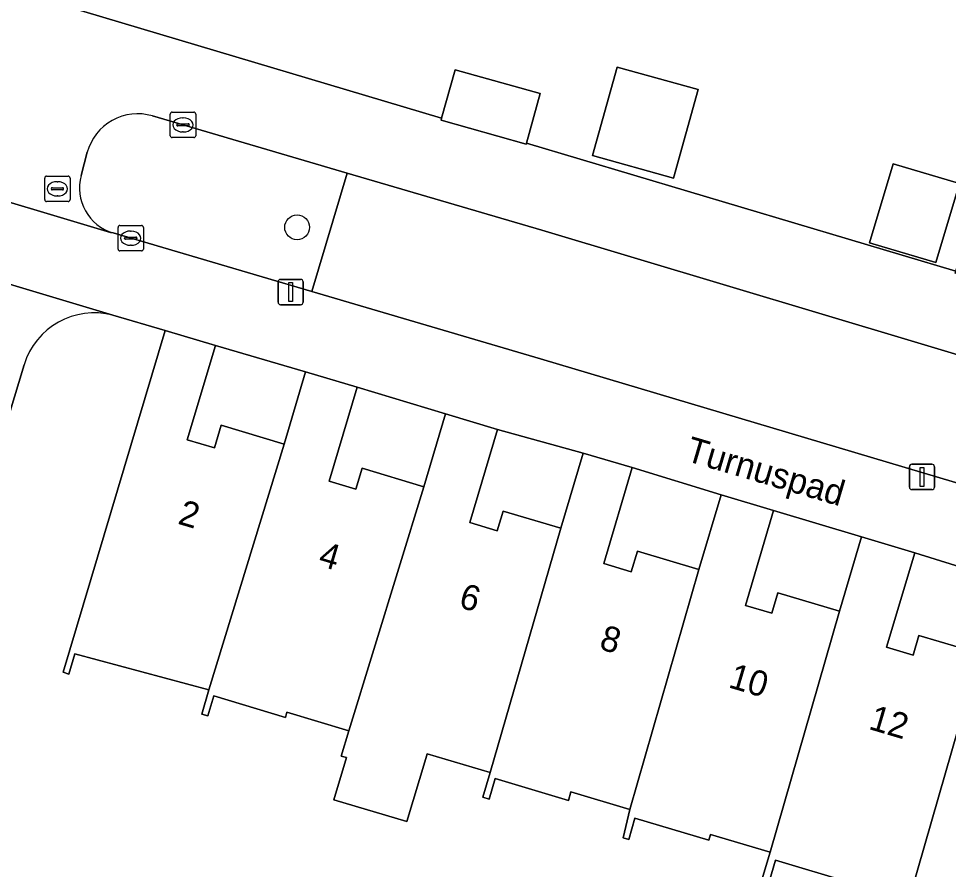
# Model space of a CAD drawing. Extents: x 162184 to 163154, y 385507 to 386516.
# Drawn here: x 162630.58 to 162667.22, y 386190.98 to 386224.51 of the extents above; entities that cross this region are included whole.
import ezdxf

# ---------------------------------------------------------------- set-up
doc = ezdxf.new("R2010")
doc.units = 0
for name, color, linetype in [('IMGEO_Boom', 7, 'Continuous'), ('IMGEO_Erf', 7, 'Continuous'), ('IMGEO_Groenvoorziening', 7, 'Continuous'), ('IMGEO_Kolk', 7, 'Continuous'), ('IMGEO_Lichtmast', 7, 'Continuous'), ('IMGEO_Openbare_ruimte_label', 7, 'Continuous'), ('IMGEO_Pand', 7, 'Continuous'), ('IMGEO_Pand_nummerreeks', 7, 'Continuous'), ('IMGEO_Rioolput', 7, 'Continuous'), ('IMGEO_Voetpad_open', 7, 'Continuous')]:
    doc.layers.add(name, color=color, linetype=linetype)

msp = doc.modelspace()

# ---------------------------------------------------------------- linework, layer by layer
at = {"layer": 'IMGEO_Boom'}
msp.add_circle((162641.558, 386216.282), 0.489, dxfattribs=at)
at = {"layer": 'IMGEO_Erf'}
for points in [[(162609.673, 386231.789), (162618.261, 386229.221), (162619.516, 386233.282), (162623.27, 386232.189), (162622.043, 386228.107), (162647.252, 386220.589), (162647.783, 386222.491), (162651.141, 386221.554), (162650.593, 386219.592), (162667.509, 386214.547), (162668.325, 386217.27), (162670.595, 386216.59), (162669.78, 386213.87), (162672.525, 386213.051), (162678.17, 386211.368)], [(162659.869, 386190.574), (162660.191, 386191.658), (162657.841, 386192.355), (162657.775, 386192.133), (162654.866, 386192.996), (162654.628, 386192.159), (162654.409, 386192.224), (162654.673, 386193.336), (162652.338, 386194.029), (162652.251, 386193.692), (162649.366, 386194.566), (162649.12, 386193.751), (162648.871, 386193.826), (162649.16, 386194.793), (162646.678, 386195.535), (162646.623, 386195.353), (162645.876, 386192.863), (162643.001, 386193.726), (162643.499, 386195.386), (162643.294, 386195.447), (162643.592, 386196.442), (162641.157, 386197.17), (162641.097, 386196.97), (162638.271, 386197.815), (162638.036, 386197.029), (162637.799, 386197.1), (162638.083, 386198.049), (162632.799, 386199.472), (162632.562, 386198.678), (162632.335, 386198.745), (162636.361, 386212.211), (162634.301, 386212.814)], [(162630.797, 386210.86), (162625.627, 386193.774)], [(162663.394, 386190.452), (162660.41, 386191.337), (162660.158, 386190.488)]]:
    msp.add_lwpolyline(points, dxfattribs=at)
for points in [[(162656.387, 386218.216), (162653.198, 386219.106), (162654.172, 386222.599), (162657.362, 386221.709)], [(162666.725, 386214.895), (162664.116, 386215.676), (162665.047, 386218.788), (162667.657, 386218.007)], [(162638.337, 386211.62), (162637.227, 386207.908), (162638.297, 386207.588), (162638.564, 386208.482), (162641.043, 386207.741), (162641.893, 386210.584)], [(162643.925, 386209.976), (162642.821, 386206.283), (162643.873, 386205.968), (162644.118, 386206.786), (162646.545, 386206.061), (162647.403, 386208.926)], [(162649.456, 386208.312), (162648.36, 386204.644), (162649.443, 386204.32), (162649.674, 386205.093), (162651.953, 386204.424), (162652.831, 386207.384)], [(162654.763, 386206.811), (162653.64, 386203.027), (162654.722, 386202.706), (162654.964, 386203.52), (162657.393, 386202.799), (162658.264, 386205.736)], [(162660.333, 386205.122), (162659.224, 386201.382), (162660.266, 386201.073), (162660.505, 386201.88), (162662.925, 386201.161), (162663.794, 386204.082)], [(162665.894, 386203.459), (162664.788, 386199.732), (162665.828, 386199.424), (162666.058, 386200.198), (162668.454, 386199.488), (162669.313, 386202.384)]]:
    msp.add_lwpolyline(points, close=True, dxfattribs=at)
msp.add_arc((162633.56, 386210.024), 2.887, 75.1335, 163.1588, dxfattribs=at)
at = {"layer": 'IMGEO_Groenvoorziening'}
for points in [[(162634.311, 386216.059), (162642.14, 386213.753), (162643.529, 386218.419), (162635.853, 386220.672)], [(162633.29, 386219.237), (162633.044, 386218.324)]]:
    msp.add_lwpolyline(points, dxfattribs=at)
msp.add_lwpolyline([(162669.521, 386210.679), (162651.203, 386216.166), (162643.529, 386218.419), (162642.14, 386213.753), (162651.146, 386211.101), (162668.123, 386206.04)], close=True, dxfattribs=at)
for centre, radius, start, end in [((162635.271, 386218.705), 2.051, 73.5107, 164.9774), ((162634.837, 386217.84), 1.857, 164.9037, 253.54)]:
    msp.add_arc(centre, radius, start, end, dxfattribs=at)
at = {"layer": 'IMGEO_Kolk'}
for p, q in [((162636.559, 386219.893), (162636.559, 386220.745)), ((162636.634, 386220.819), (162637.486, 386220.819)), ((162637.047, 386220.599), (162637.072, 386220.599)), ((162637.56, 386220.745), (162637.56, 386219.893)), ((162636.818, 386220.313), (162636.818, 386220.325)), ((162637.256, 386220.276), (162636.858, 386220.276)), ((162636.861, 386220.362), (162637.259, 386220.362)), ((162637.302, 386220.325), (162637.302, 386220.313)), ((162637.486, 386219.819), (162636.634, 386219.819)), ((162637.07, 386220.039), (162637.045, 386220.039)), ((162634.502, 386215.427), (162634.502, 386216.279)), ((162634.577, 386216.353), (162635.429, 386216.353)), ((162634.99, 386216.133), (162635.015, 386216.133)), ((162635.503, 386216.279), (162635.503, 386215.427)), ((162634.761, 386215.847), (162634.761, 386215.859)), ((162635.199, 386215.81), (162634.801, 386215.81)), ((162634.804, 386215.896), (162635.202, 386215.896)), ((162635.245, 386215.859), (162635.245, 386215.847)), ((162635.013, 386215.573), (162634.988, 386215.573)), ((162635.429, 386215.353), (162634.577, 386215.353))]:
    msp.add_line(p, q, dxfattribs=at)
for points in [[(162636.559, 386219.893), (162636.559, 386220.745)], [(162636.634, 386220.819), (162637.486, 386220.819)], [(162637.56, 386220.745), (162637.56, 386219.893)], [(162637.486, 386219.819), (162636.634, 386219.819)], [(162634.502, 386215.427), (162634.502, 386216.279)], [(162634.577, 386216.353), (162635.429, 386216.353)], [(162635.503, 386216.279), (162635.503, 386215.427)], [(162635.429, 386215.353), (162634.577, 386215.353)]]:
    msp.add_lwpolyline(points, dxfattribs=at)
for centre, radius, start, end in [((162636.636, 386220.743), 0.0765, 91.552, 178.448), ((162636.636, 386220.743), 0.0765, 91.552, 178.448), ((162637.484, 386220.743), 0.0765, 1.552, 88.448), ((162637.484, 386220.743), 0.0765, 1.552, 88.448), ((162636.858, 386220.322), 0.0403, 85.8775, 175.7526), ((162636.855, 386220.312), 0.0366, 178.938, 274.7102), ((162637.259, 386220.319), 0.043, 264.8664, 352.4533), ((162637.263, 386220.324), 0.0386, 1.7309, 96.639), ((162636.636, 386219.895), 0.0765, 181.552, 268.448), ((162636.636, 386219.895), 0.0765, 181.552, 268.448), ((162637.484, 386219.895), 0.0765, 271.552, 358.448), ((162637.484, 386219.895), 0.0765, 271.552, 358.448), ((162634.579, 386216.277), 0.0765, 91.552, 178.448), ((162634.579, 386216.277), 0.0765, 91.552, 178.448), ((162635.427, 386216.277), 0.0765, 1.552, 88.448), ((162635.427, 386216.277), 0.0765, 1.552, 88.448), ((162634.801, 386215.856), 0.0403, 85.8775, 175.7526), ((162634.798, 386215.846), 0.0366, 178.938, 274.7102), ((162635.202, 386215.853), 0.043, 264.8664, 352.4533), ((162635.206, 386215.858), 0.0386, 1.7309, 96.639), ((162634.579, 386215.429), 0.0765, 181.552, 268.448), ((162634.579, 386215.429), 0.0765, 181.552, 268.448), ((162635.427, 386215.429), 0.0765, 271.552, 358.448), ((162635.427, 386215.429), 0.0765, 271.552, 358.448)]:
    msp.add_arc(centre, radius, start, end, dxfattribs=at)
for centre, major_axis, ratio, start_param, end_param in [((162637.046, 386220.319), (-0.387, 0.002), 0.722429, 4.712389, 7.853982), ((162637.071, 386220.319), (-0.39, 0.002), 0.717154, 1.570796, 4.712389), ((162634.989, 386215.853), (-0.387, 0.002), 0.722429, 4.712389, 7.853982), ((162635.014, 386215.853), (-0.39, 0.002), 0.717154, 1.570796, 4.712389)]:
    msp.add_ellipse(centre, major_axis=major_axis, ratio=ratio, start_param=start_param, end_param=end_param, dxfattribs=at)
at = {"layer": 'IMGEO_Lichtmast'}
for p, q in [((162640.806, 386213.331), (162640.806, 386214.131)), ((162640.806, 386214.131), (162640.806, 386213.331)), ((162640.906, 386214.231), (162641.696, 386214.231)), ((162641.696, 386214.231), (162640.906, 386214.231)), ((162641.796, 386214.131), (162641.796, 386213.331)), ((162641.796, 386213.331), (162641.796, 386214.131)), ((162641.696, 386213.231), (162640.906, 386213.231)), ((162640.906, 386213.231), (162641.696, 386213.231)), ((162665.782, 386206.946), (162666.572, 386206.946)), ((162666.572, 386206.946), (162665.782, 386206.946)), ((162665.682, 386206.046), (162665.682, 386206.846)), ((162665.682, 386206.846), (162665.682, 386206.046)), ((162666.672, 386206.846), (162666.672, 386206.046)), ((162666.672, 386206.046), (162666.672, 386206.846)), ((162666.572, 386205.946), (162665.782, 386205.946)), ((162665.782, 386205.946), (162666.572, 386205.946))]:
    msp.add_line(p, q, dxfattribs=at)
for points in [[(162641.226, 386214.106), (162641.376, 386214.106), (162641.376, 386213.356), (162641.226, 386213.356), (162641.226, 386214.106)], [(162666.102, 386206.821), (162666.252, 386206.821), (162666.252, 386206.071), (162666.102, 386206.071), (162666.102, 386206.821)]]:
    msp.add_lwpolyline(points, dxfattribs=at)
for centre, start, end in [((162640.906, 386214.131), 90, 180), ((162640.906, 386214.131), 90, 180), ((162641.696, 386214.131), 0, 90), ((162641.696, 386214.131), 360, 90), ((162640.906, 386213.331), 180, 270), ((162640.906, 386213.331), 180, 270), ((162641.696, 386213.331), 270, 0), ((162641.696, 386213.331), 270, 0), ((162665.782, 386206.846), 90, 180), ((162665.782, 386206.846), 90, 180), ((162666.572, 386206.846), 0, 90), ((162666.572, 386206.846), 360, 90), ((162665.782, 386206.046), 180, 270), ((162665.782, 386206.046), 180, 270), ((162666.572, 386206.046), 270, 0), ((162666.572, 386206.046), 270, 0)]:
    msp.add_arc(centre, 0.1, start, end, dxfattribs=at)
at = {"layer": 'IMGEO_Pand'}
for points in [[(162651.141, 386221.554), (162647.783, 386222.491), (162647.252, 386220.589), (162647.227, 386220.499), (162650.585, 386219.562), (162650.593, 386219.592)], [(162656.387, 386218.216), (162657.362, 386221.709), (162654.172, 386222.599), (162653.198, 386219.106)], [(162666.725, 386214.895), (162667.657, 386218.007), (162665.047, 386218.788), (162664.116, 386215.676)], [(162636.361, 386212.211), (162632.335, 386198.745), (162632.562, 386198.678), (162632.799, 386199.472), (162638.083, 386198.049), (162641.043, 386207.741), (162638.564, 386208.482), (162638.297, 386207.588), (162637.227, 386207.908), (162638.337, 386211.62)], [(162641.893, 386210.584), (162641.043, 386207.741), (162638.083, 386198.049), (162637.799, 386197.1), (162638.036, 386197.029), (162638.271, 386197.815), (162641.097, 386196.97), (162641.157, 386197.17), (162643.592, 386196.442), (162646.545, 386206.061), (162644.118, 386206.786), (162643.873, 386205.968), (162642.821, 386206.283), (162643.925, 386209.976)], [(162647.403, 386208.926), (162646.545, 386206.061), (162643.592, 386196.442), (162643.294, 386195.447), (162643.499, 386195.386), (162643.001, 386193.726), (162645.876, 386192.863), (162646.623, 386195.353), (162646.678, 386195.535), (162649.16, 386194.793), (162651.953, 386204.424), (162649.674, 386205.093), (162649.443, 386204.32), (162648.36, 386204.644), (162649.456, 386208.312)], [(162652.831, 386207.384), (162651.953, 386204.424), (162649.16, 386194.793), (162648.871, 386193.826), (162649.12, 386193.751), (162649.366, 386194.566), (162652.251, 386193.692), (162652.338, 386194.029), (162654.673, 386193.336), (162657.393, 386202.799), (162654.964, 386203.52), (162654.722, 386202.706), (162653.64, 386203.027), (162654.763, 386206.811)], [(162658.264, 386205.736), (162657.393, 386202.799), (162654.673, 386193.336), (162654.409, 386192.224), (162654.628, 386192.159), (162654.866, 386192.996), (162657.775, 386192.133), (162657.841, 386192.355), (162660.191, 386191.658), (162662.925, 386201.161), (162660.505, 386201.88), (162660.266, 386201.073), (162659.224, 386201.382), (162660.333, 386205.122)], [(162663.794, 386204.082), (162662.925, 386201.161), (162660.191, 386191.658), (162659.869, 386190.574), (162660.158, 386190.488), (162660.41, 386191.337), (162663.394, 386190.452), (162663.455, 386190.658), (162665.724, 386189.984), (162668.454, 386199.488), (162666.058, 386200.198), (162665.828, 386199.424), (162664.788, 386199.732), (162665.894, 386203.459)], [(162669.313, 386202.384), (162668.454, 386199.488), (162665.724, 386189.984), (162665.403, 386188.904), (162664.983, 386187.492), (162670.543, 386185.797), (162670.97, 386187.241), (162674.12, 386197.756), (162671.577, 386198.51), (162671.367, 386197.801), (162670.38, 386198.094), (162671.463, 386201.746)]]:
    msp.add_lwpolyline(points, close=True, dxfattribs=at)
at = {"layer": 'IMGEO_Rioolput'}
for p, q in [((162631.611, 386217.372), (162631.611, 386218.224)), ((162631.686, 386218.298), (162632.538, 386218.298)), ((162632.099, 386218.078), (162632.124, 386218.078)), ((162632.612, 386218.224), (162632.612, 386217.372)), ((162631.87, 386217.792), (162631.87, 386217.804)), ((162632.308, 386217.755), (162631.91, 386217.755)), ((162631.913, 386217.841), (162632.311, 386217.841)), ((162632.354, 386217.804), (162632.354, 386217.792)), ((162632.538, 386217.298), (162631.686, 386217.298)), ((162632.122, 386217.518), (162632.097, 386217.518))]:
    msp.add_line(p, q, dxfattribs=at)
for points in [[(162631.611, 386217.372), (162631.611, 386218.224)], [(162631.686, 386218.298), (162632.538, 386218.298)], [(162632.612, 386218.224), (162632.612, 386217.372)], [(162632.538, 386217.298), (162631.686, 386217.298)]]:
    msp.add_lwpolyline(points, dxfattribs=at)
for centre, radius, start, end in [((162631.688, 386218.222), 0.0765, 91.552, 178.448), ((162631.688, 386218.222), 0.0765, 91.552, 178.448), ((162632.536, 386218.222), 0.0765, 1.552, 88.448), ((162632.536, 386218.222), 0.0765, 1.552, 88.448), ((162631.91, 386217.801), 0.0403, 85.8775, 175.7526), ((162631.907, 386217.791), 0.0366, 178.938, 274.7102), ((162632.311, 386217.798), 0.043, 264.8664, 352.4533), ((162632.315, 386217.803), 0.0386, 1.7309, 96.639), ((162631.688, 386217.374), 0.0765, 181.552, 268.448), ((162631.688, 386217.374), 0.0765, 181.552, 268.448), ((162632.536, 386217.374), 0.0765, 271.552, 358.448), ((162632.536, 386217.374), 0.0765, 271.552, 358.448)]:
    msp.add_arc(centre, radius, start, end, dxfattribs=at)
for centre, major_axis, ratio, start_param, end_param in [((162632.098, 386217.798), (-0.387, 0.002), 0.722429, 4.712389, 7.853982), ((162632.123, 386217.798), (-0.39, 0.002), 0.717154, 1.570796, 4.712389)]:
    msp.add_ellipse(centre, major_axis=major_axis, ratio=ratio, start_param=start_param, end_param=end_param, dxfattribs=at)
at = {"layer": 'IMGEO_Voetpad_open'}
for points in [[(162682.213, 386203.881), (162682.581, 386204.898), (162678.17, 386211.368), (162672.525, 386213.051), (162669.78, 386213.87), (162669.757, 386213.792), (162667.487, 386214.472), (162667.509, 386214.547), (162650.593, 386219.592), (162650.585, 386219.562), (162647.227, 386220.499), (162647.252, 386220.589), (162622.043, 386228.107), (162618.261, 386229.221), (162609.673, 386231.789), (162606.797, 386232.654), (162605.402, 386227.874)], [(162651.146, 386211.101), (162642.14, 386213.753), (162634.311, 386216.059), (162634.203, 386216.083), (162627.667, 386218.035), (162627.562, 386218.073), (162623.924, 386219.178), (162610.908, 386223.133), (162606.279, 386224.539)], [(162606.428, 386221.182), (162613.252, 386219.119), (162615.184, 386218.54), (162628.636, 386214.511), (162634.301, 386212.814), (162636.361, 386212.211), (162638.337, 386211.62), (162641.893, 386210.584), (162643.925, 386209.976), (162647.403, 386208.926), (162649.456, 386208.312), (162652.831, 386207.384), (162654.763, 386206.811), (162658.264, 386205.736), (162660.333, 386205.122), (162663.794, 386204.082), (162665.894, 386203.459), (162669.313, 386202.384)], [(162635.853, 386220.672), (162643.529, 386218.419), (162651.203, 386216.166), (162669.521, 386210.679), (162678.347, 386208.035)], [(162633.044, 386218.324), (162633.29, 386219.237)], [(162627.562, 386218.073), (162627.667, 386218.035), (162634.203, 386216.083), (162634.311, 386216.059)], [(162634.301, 386212.814), (162628.636, 386214.511)], [(162704.943, 386194.981), (162700.454, 386196.325), (162688.104, 386200.024), (162683.454, 386201.416), (162683.339, 386201.439), (162677.098, 386203.344), (162676.868, 386203.433), (162668.123, 386206.04), (162651.146, 386211.101)], [(162625.627, 386193.774), (162630.797, 386210.86)]]:
    msp.add_lwpolyline(points, dxfattribs=at)
for centre, radius, start, end in [((162635.271, 386218.705), 2.051, 73.5107, 164.9774), ((162634.837, 386217.84), 1.857, 164.9037, 253.54), ((162633.56, 386210.024), 2.887, 75.1335, 163.1588)]:
    msp.add_arc(centre, radius, start, end, dxfattribs=at)

# ---------------------------------------------------------------- texts
at = {"layer": 'IMGEO_Openbare_ruimte_label'}
msp.add_text('Turnuspad', height=1, rotation=343.5587, dxfattribs=at).set_placement((162656.818, 386207.094))
at = {"layer": 'IMGEO_Pand_nummerreeks'}
for s, p in [('2', (162636.817, 386204.609)), ('4', (162642.35, 386202.964)), ('6', (162647.883, 386201.32)), ('8', (162653.42, 386199.675)), ('10', (162658.511, 386198.163)), ('12', (162664.038, 386196.521))]:
    msp.add_text(s, height=1, rotation=343.4539, dxfattribs=at).set_placement(p)

doc.saveas('drawing.dxf')
